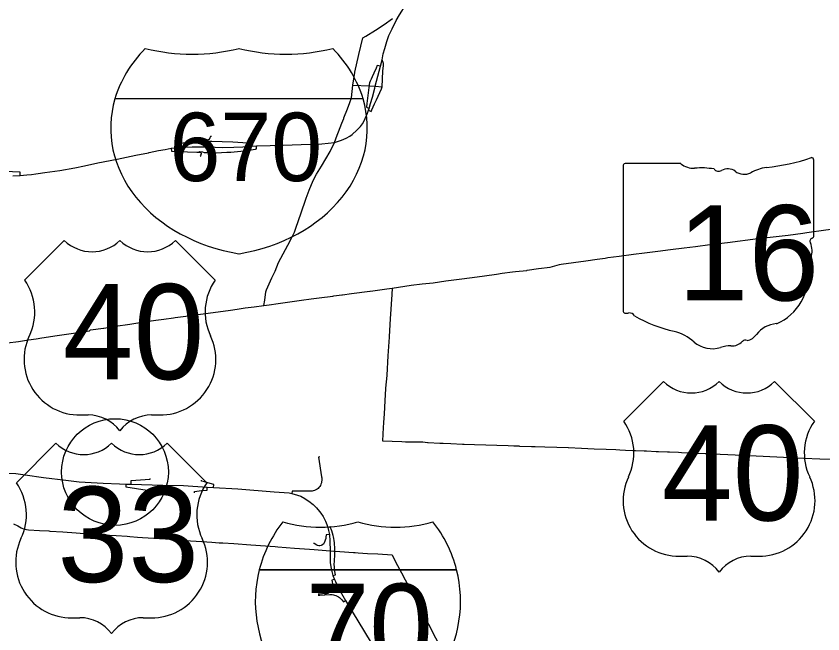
# Model space of a CAD drawing. Extents: x 0 to 34, y 0 to 22.
# Drawn here: x 5.992 to 7.083, y 16.808 to 17.644 of the extents above; entities that cross this region are included whole.
import ezdxf

# ---------------------------------------------------------------- set-up
doc = ezdxf.new("R2010")
doc.units = 0
for name, color, linetype in [('GM_X_Interchange_Ramps', 7, 'Continuous'), ('GM_X_Interstate_Route', 7, 'Continuous'), ('GM_X_Interstate_Shield', 7, 'Continuous'), ('GM_X_State_Route', 7, 'Continuous'), ('GM_X_State_Shield', 7, 'Continuous'), ('GM_X_US_Route', 7, 'Continuous'), ('GM_X_US_Shield', 7, 'Continuous'), ('SH_Text', 7, 'Continuous')]:
    doc.layers.add(name, color=color, linetype=linetype)

msp = doc.modelspace()

# ---------------------------------------------------------------- linework, layer by layer
at = {"layer": 'GM_X_Interchange_Ramps'}
for points in [[(6.4842, 17.5759), (6.48, 17.5769), (6.4784, 17.573), (6.4755, 17.5665), (6.4732, 17.5616), (6.4716, 17.5583), (6.4705, 17.5556), (6.4694, 17.5532), (6.4688, 17.5512), (6.4688, 17.5492)], [(6.4688, 17.5492), (6.4687, 17.5469), (6.466, 17.5256), (6.4654, 17.5205), (6.4692, 17.5188)], [(6.4681, 17.5162), (6.4717, 17.5147), (6.4727, 17.5169), (6.4764, 17.5251), (6.4789, 17.5305), (6.4855, 17.5453), (6.4864, 17.5479)], [(6.2558, 17.4806), (6.2546, 17.4808), (6.2537, 17.479), (6.2524, 17.4769), (6.2512, 17.476), (6.2497, 17.4752), (6.2488, 17.4749), (6.2402, 17.4746), (6.2353, 17.4744), (6.2317, 17.4741), (6.2275, 17.4735), (6.2225, 17.4727), (6.2174, 17.4715), (6.2086, 17.4698), (6.2076, 17.4696), (6.2079, 17.4655)], [(6.2538, 17.4738), (6.2518, 17.4738), (6.2486, 17.4738), (6.2488, 17.4749)], [(6.3088, 17.4676), (6.3087, 17.4718), (6.2982, 17.4721), (6.2846, 17.4729), (6.2703, 17.4733), (6.2563, 17.474), (6.2538, 17.4738)], [(6.2012, 17.4649), (6.2015, 17.461), (6.2116, 17.4605), (6.2232, 17.4602), (6.2358, 17.4597), (6.2398, 17.4596), (6.2409, 17.4594), (6.2412, 17.459), (6.2415, 17.4586), (6.2416, 17.4581), (6.2417, 17.4577), (6.2417, 17.4573), (6.2416, 17.4568), (6.2415, 17.4563), (6.2412, 17.4559), (6.2402, 17.4547), (6.2414, 17.4539)], [(6.2398, 17.4596), (6.2397, 17.4603), (6.2437, 17.4598), (6.2459, 17.4593)], [(6.2459, 17.4593), (6.2478, 17.4592), (6.2511, 17.459), (6.262, 17.4587), (6.2766, 17.4595), (6.2819, 17.4596), (6.2865, 17.4599), (6.2909, 17.4603), (6.2954, 17.4609), (6.2995, 17.4614), (6.3062, 17.4624), (6.3151, 17.4637), (6.3167, 17.4639), (6.3167, 17.4666), (6.3167, 17.4681)], [(5.9972, 17.4279), (5.9972, 17.4326), (5.9649, 17.4336)], [(6.4022, 17.0473), (6.4006, 17.0469), (6.4047, 17.0202), (6.4048, 17.0189), (6.4049, 17.0174), (6.4048, 17.0155), (6.4047, 17.0136), (6.4043, 17.0119), (6.4038, 17.0102), (6.403, 17.0084), (6.4022, 17.0073), (6.4011, 17.0058), (6.4, 17.0046), (6.3985, 17.0035), (6.397, 17.0026), (6.3951, 17.0016), (6.3934, 17.0011), (6.3919, 17.0009), (6.3723, 17.0009), (6.3648, 17.0008), (6.3643, 16.9978)], [(6.1399, 17.0104), (6.1398, 17.0067), (6.1688, 17.0023), (6.1711, 17.0018), (6.171, 17.0008)], [(6.1723, 17.0181), (6.1723, 17.0168), (6.1472, 17.0147), (6.1467, 17.0147), (6.1465, 17.0102)], [(6.2585, 17.0059), (6.2587, 17.0099), (6.2539, 17.0112), (6.2462, 17.0134), (6.2421, 17.0145), (6.2422, 17.0155)], [(6.2328, 16.9987), (6.2329, 17.0003), (6.2357, 17.0008), (6.2423, 17.0015), (6.2499, 17.0022), (6.2501, 17.0064)], [(6.4226, 16.9196), (6.4225, 16.9226), (6.4225, 16.9254), (6.4223, 16.9283), (6.422, 16.931), (6.4216, 16.934), (6.421, 16.9369), (6.4206, 16.939), (6.4201, 16.941), (6.4193, 16.9439), (6.4183, 16.9471), (6.4162, 16.9525), (6.413, 16.9518)], [(6.4152, 16.9421), (6.4108, 16.9418), (6.4105, 16.9386), (6.4102, 16.9369), (6.4096, 16.9347), (6.4091, 16.933), (6.4082, 16.931), (6.4071, 16.9293), (6.4052, 16.9278), (6.4039, 16.9272), (6.4024, 16.9268), (6.4008, 16.9268), (6.399, 16.9272), (6.398, 16.9276), (6.3946, 16.9299), (6.3939, 16.9299)], [(6.4199, 16.8865), (6.4234, 16.8877), (6.4226, 16.8923), (6.4223, 16.8945), (6.422, 16.8966), (6.4219, 16.8988), (6.4218, 16.9011), (6.4218, 16.903), (6.4219, 16.9048), (6.4224, 16.9165), (6.4225, 16.918), (6.4225, 16.9188), (6.4226, 16.9196)], [(6.4221, 16.8815), (6.4185, 16.8802), (6.4197, 16.8731), (6.4198, 16.8716), (6.4196, 16.8699), (6.4192, 16.8684), (6.4187, 16.8672), (6.4178, 16.8658), (6.4167, 16.8647), (6.4155, 16.8637), (6.4142, 16.8629), (6.4132, 16.8625), (6.4121, 16.8622), (6.4107, 16.862), (6.4095, 16.8619), (6.4086, 16.862), (6.4071, 16.8623), (6.4064, 16.8626), (6.4058, 16.8628), (6.4043, 16.8636), (6.4034, 16.8643), (6.4011, 16.8665), (6.3995, 16.8663)], [(6.4064, 16.8626), (6.4061, 16.8618), (6.4017, 16.8616), (6.4001, 16.8614)], [(6.4002, 16.8601), (6.4021, 16.8603), (6.4158, 16.8611), (6.4173, 16.8611), (6.4191, 16.8609), (6.4208, 16.8606), (6.4223, 16.8601), (6.4238, 16.8596), (6.4257, 16.8587), (6.4275, 16.8577), (6.4289, 16.8567), (6.4306, 16.8552), (6.432, 16.8537), (6.4343, 16.851), (6.437, 16.8527)]]:
    msp.add_lwpolyline(points, dxfattribs=at)
at = {"layer": 'GM_X_Interstate_Route'}
for points in [[(6.4864, 17.5846), (6.4881, 17.5924), (6.49, 17.5997), (6.493, 17.6095), (6.4958, 17.6174), (6.4999, 17.6264), (6.5056, 17.6378), (6.5101, 17.6455), (6.5186, 17.6588), (6.5262, 17.6693), (6.5284, 17.6725)], [(6.4766, 17.5461), (6.4773, 17.5488), (6.4842, 17.5759), (6.4864, 17.5846)], [(6.4221, 17.4728), (6.4317, 17.4759), (6.4379, 17.4787), (6.4429, 17.4814), (6.4458, 17.4834), (6.4524, 17.4891), (6.4574, 17.4944), (6.46, 17.4981), (6.4622, 17.5021), (6.4668, 17.5124), (6.4681, 17.5162), (6.4692, 17.5188), (6.471, 17.5254), (6.4734, 17.534), (6.4766, 17.5461)], [(6.1705, 17.4588), (6.1716, 17.459), (6.1842, 17.4619), (6.1929, 17.4633), (6.2012, 17.4649), (6.2079, 17.4655), (6.2176, 17.4661), (6.2296, 17.4666), (6.2436, 17.4667), (6.2504, 17.4666), (6.2711, 17.466), (6.286, 17.4661), (6.2983, 17.4667), (6.3088, 17.4676), (6.3167, 17.4681), (6.3176, 17.4682), (6.3525, 17.4691), (6.3771, 17.4699), (6.3941, 17.4704), (6.4051, 17.4709), (6.4134, 17.4717), (6.4221, 17.4728)], [(6.044, 17.4339), (6.0507, 17.4348), (6.0711, 17.4385), (6.0842, 17.4411), (6.1018, 17.445), (6.1282, 17.45), (6.1536, 17.4553), (6.1705, 17.4588)], [(5.9871, 17.4273), (5.9972, 17.4279), (6.0062, 17.4287), (6.0122, 17.4295), (6.0183, 17.4303)], [(6.0183, 17.4303), (6.0211, 17.4306), (6.0305, 17.4321), (6.044, 17.4339)], [(5.9547, 17.0265), (5.9579, 17.0264), (5.9794, 17.0252), (5.9913, 17.0249), (6.0038, 17.0228), (6.0286, 17.0192), (6.0586, 17.0159), (6.0769, 17.0133), (6.1094, 17.0116), (6.1314, 17.0108), (6.1399, 17.0104), (6.1465, 17.0102), (6.1901, 17.0088), (6.2178, 17.0085), (6.2501, 17.0064), (6.2585, 17.0059), (6.2912, 17.0039), (6.3405, 17.0001), (6.3607, 16.9984), (6.3643, 16.9978), (6.372, 16.9956), (6.3764, 16.9939), (6.3789, 16.9926)], [(6.3789, 16.9926), (6.3796, 16.9923), (6.3873, 16.9875), (6.3931, 16.9826), (6.3979, 16.9782), (6.402, 16.9734), (6.4037, 16.971), (6.4066, 16.9665), (6.4084, 16.9628)], [(6.4084, 16.9628), (6.41, 16.96), (6.4119, 16.9555), (6.413, 16.9518), (6.4139, 16.9476), (6.4152, 16.9421), (6.4158, 16.9332), (6.4161, 16.9202)], [(6.4161, 16.9202), (6.4162, 16.9143), (6.4163, 16.9043), (6.4177, 16.8955), (6.4199, 16.8865), (6.4221, 16.8815), (6.4233, 16.8785), (6.4251, 16.8747), (6.428, 16.8687), (6.437, 16.8527), (6.4972, 16.753), (6.526, 16.7015), (6.5471, 16.6704), (6.5586, 16.6604), (6.5628, 16.6577), (6.567, 16.6554)]]:
    msp.add_lwpolyline(points, dxfattribs=at)
at = {"layer": 'GM_X_Interstate_Shield'}
for p, q in [((6.4608, 17.5318), (6.1252, 17.5318)), ((6.4608, 17.5318), (6.1252, 17.5318)), ((6.3203, 16.8944), (6.5873, 16.8944)), ((6.5873, 16.8944), (6.3203, 16.8944)), ((6.5873, 16.8944), (6.3203, 16.8944))]:
    msp.add_line(p, q, dxfattribs=at)
for centre, start, end in [((6.4885, 16.8518), 141.669, 165.8066), ((6.4031, 17.1254), 253.0091, 286.9909), ((6.5045, 17.1254), 253.0091, 286.9909), ((6.4191, 16.8518), 14.1934, 38.331), ((6.4885, 16.8518), 165.8066, 258.463), ((6.4191, 16.8518), 281.537, 14.1934)]:
    msp.add_arc(centre, 0.1735, start, end, dxfattribs=at)
for centre, start_param, end_param in [((6.3363, 17.4921), 2.47259, 2.911027), ((6.2296, 17.7657), 4.415841, 5.008937), ((6.3563, 17.7657), 4.415841, 5.008937), ((6.2496, 17.4921), 0.230566, 0.669003), ((6.3363, 17.4921), 2.911027, 4.511031), ((6.2496, 17.4921), 4.913747, 6.513751)]:
    msp.add_ellipse(centre, major_axis=(0.2169, 0), ratio=0.8, start_param=start_param, end_param=end_param, dxfattribs=at)
at = {"layer": 'GM_X_State_Route'}
for points in [[(7.0553, 17.35), (7.0609, 17.3508), (7.0867, 17.3544), (7.1193, 17.3586), (7.153, 17.3628), (7.1626, 17.3642), (7.1839, 17.3669), (7.2302, 17.3732), (7.2795, 17.3792), (7.2819, 17.3796)], [(6.93, 17.3344), (6.9536, 17.3372), (6.9947, 17.3429), (6.9951, 17.3429), (7.0359, 17.3473), (7.0553, 17.35)], [(6.6827, 17.2997), (6.6981, 17.3019), (6.7137, 17.3039), (6.7264, 17.3076), (6.7285, 17.3079), (6.7619, 17.3126), (6.7774, 17.3148), (6.7884, 17.3163), (6.7918, 17.3168), (6.8072, 17.319), (6.8263, 17.3214), (6.8416, 17.3233), (6.8595, 17.3255), (6.8766, 17.3278), (6.8949, 17.3302), (6.9104, 17.3321), (6.9299, 17.3344), (6.93, 17.3344)], [(6.5001, 17.2755), (6.5086, 17.2769), (6.5256, 17.2795), (6.5408, 17.2813), (6.5556, 17.2829), (6.5726, 17.2853), (6.5906, 17.2876), (6.6081, 17.2899), (6.6251, 17.2923), (6.641, 17.2946), (6.6487, 17.2957), (6.6628, 17.2975), (6.6667, 17.2981), (6.6821, 17.2996), (6.6827, 17.2997)]]:
    msp.add_lwpolyline(points, dxfattribs=at)
at = {"layer": 'GM_X_State_Shield'}
for p, q in [((7.0703, 17.3466), (7.0703, 17.4489)), ((6.8126, 17.4407), (6.8126, 17.2451)), ((6.8906, 17.444), (6.8151, 17.444)), ((7.0703, 17.3466), (7.0703, 17.3466))]:
    msp.add_line(p, q, dxfattribs=at)
for centre, radius, start, end in [((6.9785, 17.7107), 0.2733, 275.8445, 288.9065), ((7.0674, 17.4493), 0.00287, 351.8621, 97.738), ((6.8155, 17.4411), 0.00299, 98.1301, 188.1301), ((6.9086, 17.4667), 0.029, 231.6195, 271.1119), ((6.9182, 17.3342), 0.104, 80.4867, 94.9883), ((6.9418, 17.4421), 0.00835, 219.7921, 297.1024), ((6.954, 17.4195), 0.0174, 54.4667, 119.1411), ((7.0133, 17.3843), 0.055, 97.3462, 120.7689), ((6.9764, 17.4505), 0.0209, 233.8562, 294.8282), ((7.0696, 17.3391), 0.00444, 107.944, 210.337), ((7.0672, 17.3462), 0.00307, 289.6038, 7.7341), ((7.0414, 17.3261), 0.0267, 340.033, 23.6496), ((7.0806, 17.3037), 0.0194, 136.8065, 186.9296), ((6.9938, 17.2907), 0.0684, 292.3089, 8.9858), ((6.8156, 17.2447), 0.00301, 171.9584, 258.3066), ((6.816, 17.2647), 0.023, 267.339, 280.6039), ((6.8207, 17.2338), 0.00829, 29.7484, 93.2717), ((6.9254, 17.4095), 0.1973, 240.4129, 257.1985), ((7.0226, 17.1902), 0.0374, 94.4031, 142.5768), ((6.8665, 17.1572), 0.0617, 47.1842, 75.836), ((6.9752, 17.2261), 0.0221, 282.8732, 323.2771), ((6.9333, 17.2328), 0.0392, 230.7004, 286.2918), ((6.9559, 17.1652), 0.0322, 85.6951, 111.2099), ((6.9588, 17.2182), 0.0209, 268.777, 315.5493), ((6.9777, 17.1992), 0.00588, 65.7517, 132.6484)]:
    msp.add_arc(centre, radius, start, end, dxfattribs=at)
at = {"layer": 'GM_X_US_Route'}
for points in [[(6.4623, 17.6152), (6.4628, 17.6155), (6.4643, 17.6164), (6.4774, 17.6247), (6.4892, 17.6322), (6.5006, 17.6403)], [(6.3266, 17.252), (6.3278, 17.2593), (6.3293, 17.2704), (6.3303, 17.2732), (6.3372, 17.2895), (6.3417, 17.2985), (6.3465, 17.3103), (6.3591, 17.3337), (6.3654, 17.3459), (6.3682, 17.3515), (6.3707, 17.3592), (6.3724, 17.3645), (6.378, 17.3803), (6.3826, 17.3933), (6.384, 17.3973), (6.3877, 17.4082), (6.3934, 17.4213), (6.3978, 17.4296), (6.4046, 17.4404), (6.4162, 17.4606), (6.4221, 17.4728), (6.4259, 17.4825), (6.4276, 17.4869), (6.4321, 17.4986), (6.4346, 17.505), (6.4349, 17.5058), (6.4396, 17.5183), (6.4428, 17.5269), (6.4451, 17.5331), (6.447, 17.5503), (6.4495, 17.5672), (6.4496, 17.5677), (6.455, 17.5919), (6.4603, 17.6142), (6.4623, 17.6152)], [(6.4864, 17.5479), (6.4877, 17.5691), (6.4882, 17.577), (6.4882, 17.5795), (6.4864, 17.5846)], [(6.447, 17.5503), (6.4688, 17.5492), (6.4773, 17.5488), (6.4864, 17.5479)], [(6.4331, 17.2665), (6.4453, 17.2681), (6.4701, 17.2714), (6.4703, 17.2715), (6.474, 17.272), (6.4927, 17.2745), (6.5001, 17.2755)], [(6.5001, 17.2755), (6.4995, 17.2671), (6.4975, 17.2342)], [(6.346, 17.2548), (6.3775, 17.2593), (6.3905, 17.261), (6.4012, 17.2624), (6.4199, 17.2649), (6.4212, 17.2651), (6.4318, 17.2664), (6.4323, 17.2664), (6.433, 17.2665), (6.4331, 17.2665)], [(6.2378, 17.2399), (6.2814, 17.2459), (6.2905, 17.2472), (6.3015, 17.2487), (6.3135, 17.2504), (6.3266, 17.252)], [(6.3266, 17.252), (6.3339, 17.2531)], [(6.3339, 17.2531), (6.3339, 17.2531), (6.346, 17.2548)], [(6.1806, 17.2323), (6.1915, 17.2337), (6.2044, 17.2353), (6.2067, 17.2356), (6.2353, 17.2396), (6.2378, 17.2399), (6.2378, 17.2399)], [(5.9473, 17.1967), (5.9567, 17.1983), (5.9584, 17.1986), (5.96, 17.1988), (5.9755, 17.2007), (5.9798, 17.2014), (5.9945, 17.2035), (6.0082, 17.2055), (6.0187, 17.207), (6.0261, 17.2082), (6.0411, 17.2105), (6.0439, 17.2108), (6.0563, 17.2127), (6.0722, 17.2151), (6.0906, 17.2178), (6.0921, 17.2189), (6.1096, 17.2215), (6.11, 17.2216), (6.1226, 17.2235), (6.1257, 17.224), (6.1453, 17.227), (6.1617, 17.2294), (6.1806, 17.2323)], [(6.4975, 17.2342), (6.4975, 17.2341), (6.496, 17.2102), (6.4959, 17.2094), (6.4943, 17.1839), (6.4927, 17.1578), (6.4927, 17.1572), (6.4912, 17.1404), (6.4911, 17.1397), (6.4902, 17.1229), (6.4891, 17.1056), (6.4891, 17.1052), (6.4888, 17.0999), (6.4884, 17.0932)], [(6.4884, 17.0932), (6.488, 17.0871), (6.4869, 17.0689)], [(6.4869, 17.0689), (6.5132, 17.0679), (6.5182, 17.0677), (6.5417, 17.0674), (6.5481, 17.0666), (6.5486, 17.0666), (6.5644, 17.0659), (6.5692, 17.0657), (6.5795, 17.0653), (6.5952, 17.0646), (6.5975, 17.0645), (6.6114, 17.0639), (6.6116, 17.0639), (6.6266, 17.0634), (6.6417, 17.0629), (6.6569, 17.0624), (6.6645, 17.0622)], [(6.6645, 17.0622), (6.6653, 17.0622), (6.6716, 17.062), (6.6723, 17.0619), (6.6886, 17.0614), (6.6933, 17.0613), (6.7066, 17.0608), (6.7226, 17.0603), (6.738, 17.0598), (6.7385, 17.0598), (6.7562, 17.059), (6.7731, 17.0583), (6.7896, 17.0576), (6.8028, 17.057), (6.8078, 17.0568), (6.8158, 17.0564), (6.8255, 17.056), (6.8293, 17.0558), (6.8408, 17.0553), (6.8439, 17.0552), (6.8573, 17.0546), (6.8602, 17.0545), (6.8724, 17.054), (6.8754, 17.0539), (6.8873, 17.0534), (6.8916, 17.0532), (6.9002, 17.0529), (6.9126, 17.0521), (6.9234, 17.0519), (6.9246, 17.0518)], [(6.9246, 17.0518), (6.9336, 17.0514), (6.9641, 17.05), (6.9731, 17.0494), (6.9741, 17.0494), (7.0205, 17.0472), (7.0569, 17.0455), (7.0572, 17.0455), (7.0783, 17.0447), (7.1275, 17.0431), (7.1283, 17.0431), (7.1589, 17.0416), (7.1726, 17.0411), (7.1858, 17.0405), (7.1995, 17.0395), (7.2116, 17.0389), (7.2121, 17.0389), (7.2276, 17.0382), (7.2338, 17.0379), (7.2573, 17.0368), (7.258, 17.0368), (7.2823, 17.0358)], [(5.988, 16.9567), (5.994, 16.9537), (5.9983, 16.9514), (6.0024, 16.9495), (6.0054, 16.9489), (6.0081, 16.9487), (6.0231, 16.9477), (6.0356, 16.947), (6.0372, 16.9469), (6.0545, 16.9456), (6.0726, 16.9444), (6.0893, 16.9432), (6.0985, 16.9426), (6.1089, 16.9419), (6.127, 16.9408), (6.1419, 16.9397), (6.1454, 16.9394), (6.1555, 16.9387), (6.1623, 16.9383), (6.1779, 16.9373), (6.1856, 16.9368), (6.1934, 16.9362), (6.213, 16.9348), (6.2275, 16.9337), (6.2426, 16.9327), (6.2562, 16.9318), (6.266, 16.9311), (6.2709, 16.9307), (6.2859, 16.9298), (6.3089, 16.9281), (6.3417, 16.9258), (6.3456, 16.9255), (6.3681, 16.9238), (6.3881, 16.9223)], [(6.3881, 16.9223), (6.3948, 16.9218), (6.4161, 16.9202), (6.421, 16.9198)], [(6.421, 16.9198), (6.4226, 16.9196), (6.4292, 16.9192), (6.4477, 16.9179), (6.4501, 16.9178)], [(6.4501, 16.9178), (6.4542, 16.9175), (6.4668, 16.9166), (6.4806, 16.9158), (6.5, 16.9145)], [(6.5, 16.9145), (6.5006, 16.9131), (6.5072, 16.9003), (6.5125, 16.8905), (6.5176, 16.881), (6.5248, 16.8672), (6.5344, 16.8491), (6.5391, 16.8401), (6.5589, 16.8025), (6.5709, 16.7796), (6.5744, 16.7728), (6.5774, 16.7669), (6.5789, 16.764)]]:
    msp.add_lwpolyline(points, dxfattribs=at)
at = {"layer": 'GM_X_US_Shield'}
for p, q in [((6.0567, 17.3401), (6.003, 17.2864)), ((6.2607, 17.2864), (6.207, 17.3401)), ((6.8671, 17.149), (6.8134, 17.0954)), ((7.0711, 17.0954), (7.0174, 17.149)), ((6.0782, 17.1039), (6.0889, 17.1039)), ((6.1748, 17.1039), (6.1856, 17.1039)), ((6.0454, 17.0658), (5.9918, 17.0121)), ((6.2494, 17.0121), (6.1958, 17.0658)), ((6.8886, 16.9128), (6.8993, 16.9128)), ((6.9852, 16.9128), (6.9959, 16.9128)), ((6.0669, 16.8296), (6.0776, 16.8296)), ((6.1635, 16.8296), (6.1743, 16.8296))]:
    msp.add_line(p, q, dxfattribs=at)
for centre, radius, start, end in [((6.0943, 17.3785), 0.0537, 225.573, 314.427), ((6.1695, 17.3785), 0.0537, 225.573, 314.427), ((5.9415, 17.2433), 0.0752, 334.5471, 35.0009), ((6.3223, 17.2433), 0.0752, 144.9991, 205.4529), ((6.0774, 17.1791), 0.0752, 154.8319, 270.6383), ((6.1864, 17.1791), 0.0752, 269.3617, 25.1681), ((6.9047, 17.1874), 0.0537, 225.573, 314.427), ((6.9798, 17.1874), 0.0537, 225.573, 314.427), ((6.0889, 17.0502), 0.0537, 36.8699, 90), ((6.1748, 17.0502), 0.0537, 90, 143.1301), ((6.7518, 17.0523), 0.0752, 334.5471, 35.0009), ((7.1327, 17.0523), 0.0752, 144.9991, 205.4529), ((6.083, 17.1041), 0.0537, 225.573, 314.427), ((6.1582, 17.1041), 0.0537, 225.573, 314.427), ((5.9302, 16.969), 0.0752, 334.5471, 35.0009), ((6.311, 16.969), 0.0752, 144.9991, 205.4529), ((6.8877, 16.988), 0.0752, 154.8319, 270.6383), ((6.9968, 16.988), 0.0752, 269.3617, 25.1681), ((6.0661, 16.9047), 0.0752, 154.8319, 270.6383), ((6.1751, 16.9047), 0.0752, 269.3617, 25.1681), ((6.8993, 16.8591), 0.0537, 36.8699, 90), ((6.9852, 16.8591), 0.0537, 90, 143.1301), ((6.0776, 16.7759), 0.0537, 36.8699, 90), ((6.1635, 16.7759), 0.0537, 90, 143.1301)]:
    msp.add_arc(centre, radius, start, end, dxfattribs=at)
at = {"layer": 'SH_Text'}
msp.add_circle((6.1252, 17.0267), 0.0722, dxfattribs=at)

# ---------------------------------------------------------------- texts
at = {"layer": 'GM_X_Interstate_Shield'}
for s, height, p in [('670', 0.09255, (6.1989, 17.4204)), ('70', 0.11569, (6.3832, 16.7599))]:
    msp.add_text(s, height=height, dxfattribs=at).set_placement(p)
at = {"layer": 'GM_X_State_Shield'}
msp.add_text('16', height=0.12885, dxfattribs=at).set_placement((6.8861, 17.2589))
at = {"layer": 'GM_X_US_Shield'}
for s, p in [('40', (6.0545, 17.1522)), ('40', (6.8649, 16.9611)), ('33', (6.0473, 16.8779))]:
    msp.add_text(s, height=0.12885, dxfattribs=at).set_placement(p)

doc.saveas('drawing.dxf')
